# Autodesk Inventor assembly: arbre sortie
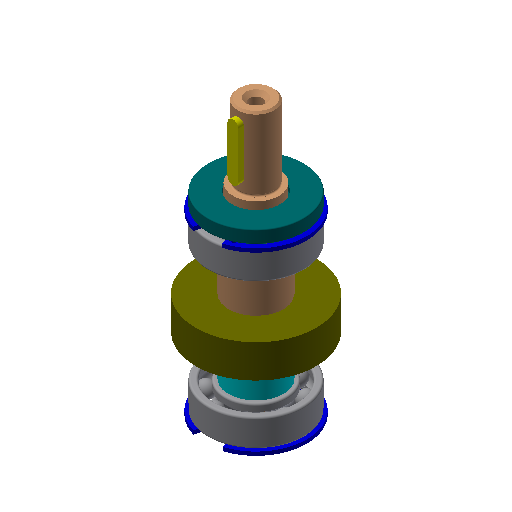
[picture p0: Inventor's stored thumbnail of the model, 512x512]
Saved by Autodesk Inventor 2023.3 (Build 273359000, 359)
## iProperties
Created: 2012-12
Part Number: arbre sortie
Document SubType Name: Assembly
Designer: jost thierry
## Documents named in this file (9)
- E:\Dossier technique\Reducteur\TD02-Reducteur S37\TD02-Reducteur-Ressources\TD02-Reduct-3D\arbre sortie.iam
- E:\Dossier technique\Reducteur\TD02-Reducteur S37\TD02-Reducteur-Ressources\TD02-Reduct-3D\ARBRE DE SORTIE.ipt
- E:\Dossier technique\Reducteur\TD02-Reducteur S37\TD02-Reducteur-Ressources\TD02-Reduct-3D\ROUE 3.ipt
- E:\Dossier technique\Reducteur\TD02-Reducteur S37\TD02-Reducteur-Ressources\TD02-Reduct-3D\CLAVETTE D.ipt
- E:\Dossier technique\Reducteur\TD02-Reducteur S37\TD02-Reducteur-Ressources\TD02-Reduct-3D\BAGUE.ipt
- E:\Dossier technique\Reducteur\TD02-Reducteur S37\TD02-Reducteur-Ressources\TD02-Reduct-3D\CLAVETTE  A.ipt
- E:\Dossier technique\Reducteur\TD02-Reducteur S37\TD02-Reducteur-Ressources\TD02-Reduct-3D\roulement 25 52 15.iam
- E:\Dossier technique\Reducteur\TD02-Reducteur S37\TD02-Reducteur-Ressources\TD02-Reduct-3D\anneauint55.ipt
- E:\Dossier technique\Reducteur\TD02-Reducteur S37\TD02-Reducteur-Ressources\TD02-Reduct-3D\joint à lèvres 52.ipt
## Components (10 placed, 8 different names)
1. ARBRE DE SORTIE:1
2. ROUE 3:1
3. CLAVETTE D:1
4. BAGUE:1
5. CLAVETTE  A:1
6. roulement 25 52 15:3 [sub-assembly]
7. roulement 25 52 15:4 [sub-assembly]
8. anneauint55:3
9. anneauint55:4
10. joint à lèvres 52:2
